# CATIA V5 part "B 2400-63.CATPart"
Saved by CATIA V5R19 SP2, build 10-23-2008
Part number: B 2400-63
Bounding box of the stored display mesh (mm): x -37.351 to 37.351, y -37.351 to 37.351, z 0 to 237
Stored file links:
  C:\Users\Bora\Desktop\3D Katı model\B serisi\B 2400\B 2400-63.CATPart
  C:\Program Files\Dassault Systemes\B19\intel_a\reffiles\standard\MetricThickPitch.txt
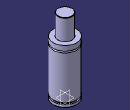
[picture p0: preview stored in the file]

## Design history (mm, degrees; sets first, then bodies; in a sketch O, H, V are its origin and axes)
Body1 (main body)
  Sketch1 on yz-plane, origin (0, 0, 0), H (0, 1, 0), V (0, 0, 1)
    point P1 (37.5, 155.5)
    point P2 (37.5, 150.5)
    point P3 (37.5, 155.5)
    point P6 (37.5, 150.5)
    point P9 (22.5, 236)
    point P11 (22.5, 236)
    arc A1 centre (37.5, 153) radius 2.5 from (37.5, 155.5) to (37.5, 150.5) ccw
    line L1 (37.5, 155.5) -> (37.5, 171)
    line L2 (37.5, 13) -> (37.5, 150.5)
    line L3 (33.5, 13) -> (33.5, 8)
    arc A2 centre (21.5, 236) radius 1 from (22.5, 236) to (21.5, 237) ccw
    line L4 (22.5, 236) -> (22.5, 171)
    line L5 (37.5, 0) -> (37.5, 8)
    line L6 (21.5, 237) -> (0, 237)
    point P15 (0, 237)
    line L7 (22.5, 171) -> (37.5, 171)
    line L8 (0, 0) -> (37.5, 0)
    line L9 (33.5, 13) -> (37.5, 13)
    line L10 (33.5, 8) -> (37.5, 8)
    coincidence: P15 V, P1 P3, P2 P6, P9 P11
    tangency: L6 A2
    horizontal: L7 H, L8 H, L9 H, L10 H
  Shaft1: profile Sketch1, axis Sketch1.V, angle 360
  Sketch2 on face of Shaft1 from Sketch1.L8, origin (0, 0, 0), H (1, 0, 0), V (0, -1, 0)
    point P1 (20, 0)
    distance P1 V = 20
  Hole1: placed by Sketch2, at (20, 0, 0) direction (0, 0, 1), diameter 6.647, depth 13, threaded "M8", thread diameter 8, thread depth 13, pitch 1.25
  CircPattern1: of Hole1, instances 4, angular step 90, axis from xy-plane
